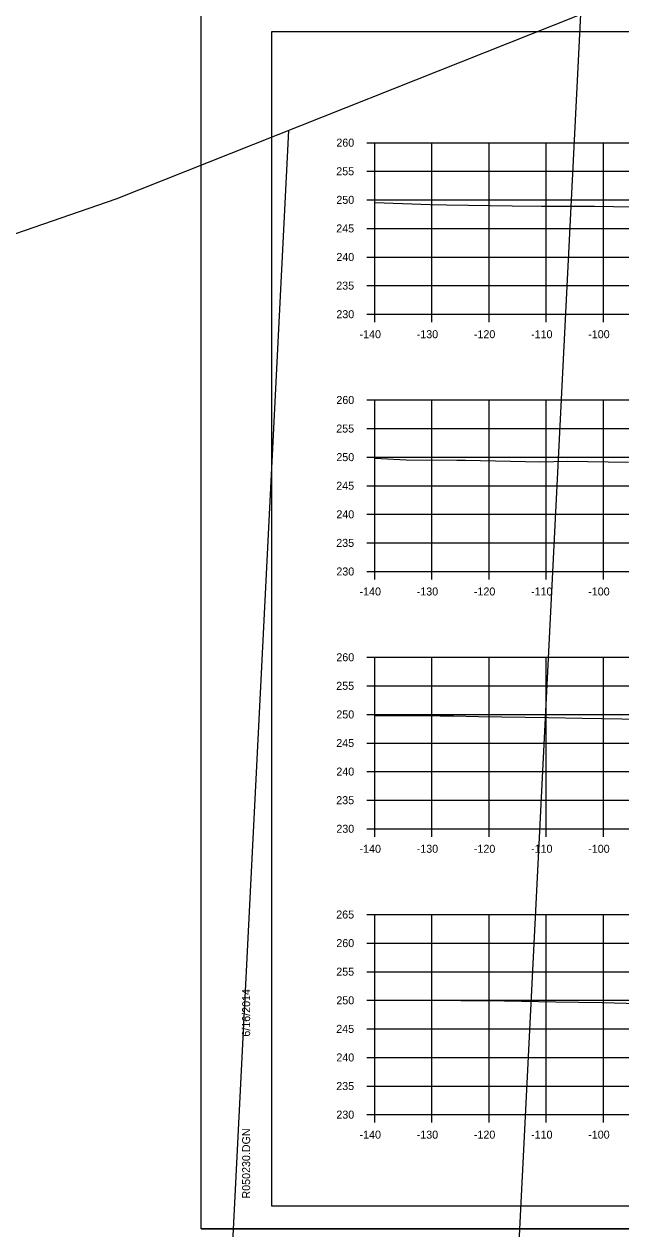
# Model space of a CAD drawing. Extents: x 1300404 to 1323571, y 234004 to 252077.
# Drawn here: x 1315515.9 to 1315620.3, y 242768.5 to 242979.2 of the extents above; entities that cross this region are included whole.
import ezdxf

# ---------------------------------------------------------------- set-up
doc = ezdxf.new("R2010")
doc.units = 0
for name, color, linetype in [('Default', 7, 'Continuous'), ('R_Axis', 7, 'Continuous'), ('R_Axis Annot', 7, 'Continuous'), ('R_Border', 7, 'Continuous'), ('R_Exist Surface', 7, 'Continuous'), ('R_Floodway', 7, 'Continuous'), ('R_Grid', 7, 'Continuous'), ('R_No Plot', 7, 'Continuous')]:
    doc.layers.add(name, color=color, linetype=linetype)

msp = doc.modelspace()

# ---------------------------------------------------------------- linework, layer by layer
at = {"layer": 'Default'}
for p, q in [((1315559.28, 242977.92), (1315875.46, 242977.92)), ((1315559.28, 242772.46), (1315559.28, 242977.92)), ((1315875.46, 242772.46), (1315559.28, 242772.46))]:
    msp.add_line(p, q, dxfattribs=at)
at = {"layer": 'R_Axis'}
for p, q in [((1315575.88, 242958.46), (1315577.28, 242958.46)), ((1315577.28, 242928.46), (1315577.28, 242958.46)), ((1315575.88, 242953.46), (1315577.28, 242953.46)), ((1315575.88, 242948.46), (1315577.28, 242948.46)), ((1315575.88, 242943.46), (1315577.28, 242943.46)), ((1315575.88, 242938.46), (1315577.28, 242938.46)), ((1315575.88, 242933.46), (1315577.28, 242933.46)), ((1315575.88, 242928.46), (1315577.28, 242928.46)), ((1315577.28, 242928.46), (1315857.28, 242928.46)), ((1315577.28, 242927.06), (1315577.28, 242928.46)), ((1315587.28, 242927.06), (1315587.28, 242928.46)), ((1315597.28, 242927.06), (1315597.28, 242928.46)), ((1315607.28, 242927.06), (1315607.28, 242928.46)), ((1315617.28, 242927.06), (1315617.28, 242928.46)), ((1315575.88, 242913.46), (1315577.28, 242913.46)), ((1315577.28, 242883.46), (1315577.28, 242913.46)), ((1315575.88, 242908.46), (1315577.28, 242908.46)), ((1315575.88, 242903.46), (1315577.28, 242903.46)), ((1315575.88, 242898.46), (1315577.28, 242898.46)), ((1315575.88, 242893.46), (1315577.28, 242893.46)), ((1315575.88, 242888.46), (1315577.28, 242888.46)), ((1315575.88, 242883.46), (1315577.28, 242883.46)), ((1315577.28, 242883.46), (1315857.28, 242883.46)), ((1315577.28, 242882.06), (1315577.28, 242883.46)), ((1315587.28, 242882.06), (1315587.28, 242883.46)), ((1315597.28, 242882.06), (1315597.28, 242883.46)), ((1315607.28, 242882.06), (1315607.28, 242883.46)), ((1315617.28, 242882.06), (1315617.28, 242883.46)), ((1315575.88, 242868.46), (1315577.28, 242868.46)), ((1315577.28, 242838.46), (1315577.28, 242868.46)), ((1315575.88, 242863.46), (1315577.28, 242863.46)), ((1315575.88, 242858.46), (1315577.28, 242858.46)), ((1315575.88, 242853.46), (1315577.28, 242853.46)), ((1315575.88, 242848.46), (1315577.28, 242848.46)), ((1315575.88, 242843.46), (1315577.28, 242843.46)), ((1315575.88, 242838.46), (1315577.28, 242838.46)), ((1315577.28, 242838.46), (1315857.28, 242838.46)), ((1315577.28, 242837.06), (1315577.28, 242838.46)), ((1315587.28, 242837.06), (1315587.28, 242838.46)), ((1315597.28, 242837.06), (1315597.28, 242838.46)), ((1315607.28, 242837.06), (1315607.28, 242838.46)), ((1315617.28, 242837.06), (1315617.28, 242838.46)), ((1315575.88, 242823.46), (1315577.28, 242823.46)), ((1315577.28, 242788.46), (1315577.28, 242823.46)), ((1315575.88, 242818.46), (1315577.28, 242818.46)), ((1315575.88, 242813.46), (1315577.28, 242813.46)), ((1315575.88, 242808.46), (1315577.28, 242808.46)), ((1315575.88, 242803.46), (1315577.28, 242803.46)), ((1315575.88, 242798.46), (1315577.28, 242798.46)), ((1315575.88, 242793.46), (1315577.28, 242793.46)), ((1315575.88, 242788.46), (1315577.28, 242788.46)), ((1315577.28, 242788.46), (1315857.28, 242788.46)), ((1315577.28, 242787.06), (1315577.28, 242788.46)), ((1315587.28, 242787.06), (1315587.28, 242788.46)), ((1315597.28, 242787.06), (1315597.28, 242788.46)), ((1315607.28, 242787.06), (1315607.28, 242788.46)), ((1315617.28, 242787.06), (1315617.28, 242788.46))]:
    msp.add_line(p, q, dxfattribs=at)
at = {"layer": 'R_Border'}
msp.add_line((1315559.28, 242772.46), (1315559.28, 242772.46), dxfattribs=at)
at = {"layer": 'R_Exist Surface'}
for points in [[(1315577.28, 242947.97), (1315586.95, 242947.64), (1315589.81, 242947.59), (1315601.32, 242947.43), (1315606.42, 242947.33), (1315615.71, 242947.33), (1315632.36, 242947.05)], [(1315577.28, 242903.28), (1315582.76, 242902.99), (1315591.6, 242902.94), (1315593.13, 242902.92), (1315606.24, 242902.66), (1315610.92, 242902.73), (1315621.64, 242902.57)], [(1315577.28, 242858.27), (1315579.32, 242858.27), (1315588.71, 242858.21), (1315591.05, 242858.19), (1315595.44, 242858.09), (1315607.68, 242857.92), (1315613.53, 242857.78), (1315623.94, 242857.62)], [(1315577.28, 242808.49), (1315587.14, 242808.49), (1315592.31, 242808.45), (1315599.96, 242808.35), (1315608.89, 242808.18), (1315617.04, 242808.07), (1315627.49, 242807.79)]]:
    msp.add_lwpolyline(points, dxfattribs=at)
at = {"layer": 'R_Floodway'}
for p, q in [((1315571.51, 242146.87), (1315613.29, 242980.93)), ((1315520.65, 242130.98), (1315562.21, 242960.62))]:
    msp.add_line(p, q, dxfattribs=at)
msp.add_lwpolyline([(1314910.15, 242704.13), (1315187.43, 242830.5), (1315532.05, 242948.63), (1315904.78, 243096.81), (1316163.13, 243182.99), (1316319.99, 243223.48), (1316365.84, 243269.57), (1316331.91, 243414.03), (1316310.53, 243519.15), (1316371.54, 243772.55), (1316440.41, 243940.88), (1316516.3, 244055.61), (1316743.63, 244150.62), (1316811.07, 244193.2), (1316966.08, 244536.23), (1317034.84, 244653.74), (1317199.18, 244747.09), (1317449.44, 244816.75), (1317656.98, 244903.07)], dxfattribs=at)
at = {"layer": 'R_Grid'}
for p, q in [((1315577.28, 242958.46), (1315857.28, 242958.46)), ((1315577.28, 242928.46), (1315577.28, 242958.46)), ((1315587.28, 242928.46), (1315587.28, 242958.46)), ((1315597.28, 242928.46), (1315597.28, 242958.46)), ((1315607.28, 242928.46), (1315607.28, 242958.46)), ((1315617.28, 242928.46), (1315617.28, 242958.46)), ((1315577.28, 242953.46), (1315857.28, 242953.46)), ((1315577.28, 242948.46), (1315857.28, 242948.46)), ((1315577.28, 242943.46), (1315857.28, 242943.46)), ((1315577.28, 242938.46), (1315857.28, 242938.46)), ((1315577.28, 242933.46), (1315857.28, 242933.46)), ((1315577.28, 242928.46), (1315857.28, 242928.46)), ((1315577.28, 242913.46), (1315857.28, 242913.46)), ((1315577.28, 242883.46), (1315577.28, 242913.46)), ((1315587.28, 242883.46), (1315587.28, 242913.46)), ((1315597.28, 242883.46), (1315597.28, 242913.46)), ((1315607.28, 242883.46), (1315607.28, 242913.46)), ((1315617.28, 242883.46), (1315617.28, 242913.46)), ((1315577.28, 242908.46), (1315857.28, 242908.46)), ((1315577.28, 242903.46), (1315857.28, 242903.46)), ((1315577.28, 242898.46), (1315857.28, 242898.46)), ((1315577.28, 242893.46), (1315857.28, 242893.46)), ((1315577.28, 242888.46), (1315857.28, 242888.46)), ((1315577.28, 242883.46), (1315857.28, 242883.46)), ((1315577.28, 242868.46), (1315857.28, 242868.46)), ((1315577.28, 242838.46), (1315577.28, 242868.46)), ((1315587.28, 242838.46), (1315587.28, 242868.46)), ((1315597.28, 242838.46), (1315597.28, 242868.46)), ((1315607.28, 242838.46), (1315607.28, 242868.46)), ((1315617.28, 242838.46), (1315617.28, 242868.46)), ((1315577.28, 242863.46), (1315857.28, 242863.46)), ((1315577.28, 242858.46), (1315857.28, 242858.46)), ((1315577.28, 242853.46), (1315857.28, 242853.46)), ((1315577.28, 242848.46), (1315857.28, 242848.46)), ((1315577.28, 242843.46), (1315857.28, 242843.46)), ((1315577.28, 242838.46), (1315857.28, 242838.46)), ((1315577.28, 242823.46), (1315857.28, 242823.46)), ((1315577.28, 242788.46), (1315577.28, 242823.46)), ((1315587.28, 242788.46), (1315587.28, 242823.46)), ((1315597.28, 242788.46), (1315597.28, 242823.46)), ((1315607.28, 242788.46), (1315607.28, 242823.46)), ((1315617.28, 242788.46), (1315617.28, 242823.46)), ((1315577.28, 242818.46), (1315857.28, 242818.46)), ((1315577.28, 242813.46), (1315857.28, 242813.46)), ((1315577.28, 242808.46), (1315857.28, 242808.46)), ((1315577.28, 242803.46), (1315857.28, 242803.46)), ((1315577.28, 242798.46), (1315857.28, 242798.46)), ((1315577.28, 242793.46), (1315857.28, 242793.46)), ((1315577.28, 242788.46), (1315857.28, 242788.46))]:
    msp.add_line(p, q, dxfattribs=at)
at = {"layer": 'R_No Plot'}
msp.add_line((1315546.87, 242768.48), (1315880.21, 242768.48), dxfattribs=at)
for points in [[(1315546.87, 242981.81), (1315880.21, 242981.81), (1315880.21, 242768.47), (1315546.87, 242768.47)], [(1315793.2, 242977.92), (1315793.2, 242968.04), (1315828.93, 242968.04), (1315828.93, 242965.12), (1315852.13, 242965.12), (1315852.13, 242943), (1315875.46, 242943), (1315875.46, 242772.46), (1315559.28, 242772.46), (1315559.28, 242977.92)]]:
    msp.add_lwpolyline(points, close=True, dxfattribs=at)

# ---------------------------------------------------------------- texts
at = {"layer": 'R_Axis'}
for p in [(1315577.28, 242928.46), (1315577.28, 242883.46), (1315577.28, 242838.46), (1315577.28, 242788.46)]:
    msp.add_text('-', height=0.0001, dxfattribs=at).set_placement(p)
at = {"layer": 'R_Axis Annot'}
for s, p in [('260', (1315570.55, 242957.76)), ('255', (1315570.53, 242952.76)), ('250', (1315570.55, 242947.76)), ('245', (1315570.53, 242942.76)), ('240', (1315570.55, 242937.76)), ('235', (1315570.53, 242932.76)), ('230', (1315570.55, 242927.76)), ('-140', (1315574.61, 242924.26)), ('-130', (1315584.61, 242924.26)), ('-120', (1315594.61, 242924.26)), ('-110', (1315604.61, 242924.26)), ('-100', (1315614.61, 242924.26)), ('260', (1315570.55, 242912.76)), ('255', (1315570.53, 242907.76)), ('250', (1315570.55, 242902.76)), ('245', (1315570.53, 242897.76)), ('240', (1315570.55, 242892.76)), ('235', (1315570.53, 242887.76)), ('230', (1315570.55, 242882.76)), ('-140', (1315574.61, 242879.26)), ('-130', (1315584.61, 242879.26)), ('-120', (1315594.61, 242879.26)), ('-110', (1315604.61, 242879.26)), ('-100', (1315614.61, 242879.26)), ('260', (1315570.55, 242867.76)), ('255', (1315570.53, 242862.76)), ('250', (1315570.55, 242857.76)), ('245', (1315570.53, 242852.76)), ('240', (1315570.55, 242847.76)), ('235', (1315570.53, 242842.76)), ('230', (1315570.55, 242837.76)), ('-140', (1315574.61, 242834.26)), ('-130', (1315584.61, 242834.26)), ('-120', (1315594.61, 242834.26)), ('-110', (1315604.61, 242834.26)), ('-100', (1315614.61, 242834.26)), ('265', (1315570.53, 242822.76)), ('260', (1315570.55, 242817.76)), ('255', (1315570.53, 242812.76)), ('250', (1315570.55, 242807.76)), ('245', (1315570.53, 242802.76)), ('240', (1315570.55, 242797.76)), ('235', (1315570.53, 242792.76)), ('230', (1315570.55, 242787.76)), ('-140', (1315574.61, 242784.26)), ('-130', (1315584.61, 242784.26)), ('-120', (1315594.61, 242784.26)), ('-110', (1315604.61, 242784.26)), ('-100', (1315614.61, 242784.26))]:
    msp.add_text(s, height=1.4, dxfattribs=at).set_placement(p)
at = {"layer": 'R_Border'}
for s, p in [('6/16/2014', (1315555.47, 242802.1)), ('R050230.DGN', (1315555.47, 242773.78))]:
    msp.add_text(s, height=1.4, rotation=90, dxfattribs=at).set_placement(p)

doc.saveas('drawing.dxf')
